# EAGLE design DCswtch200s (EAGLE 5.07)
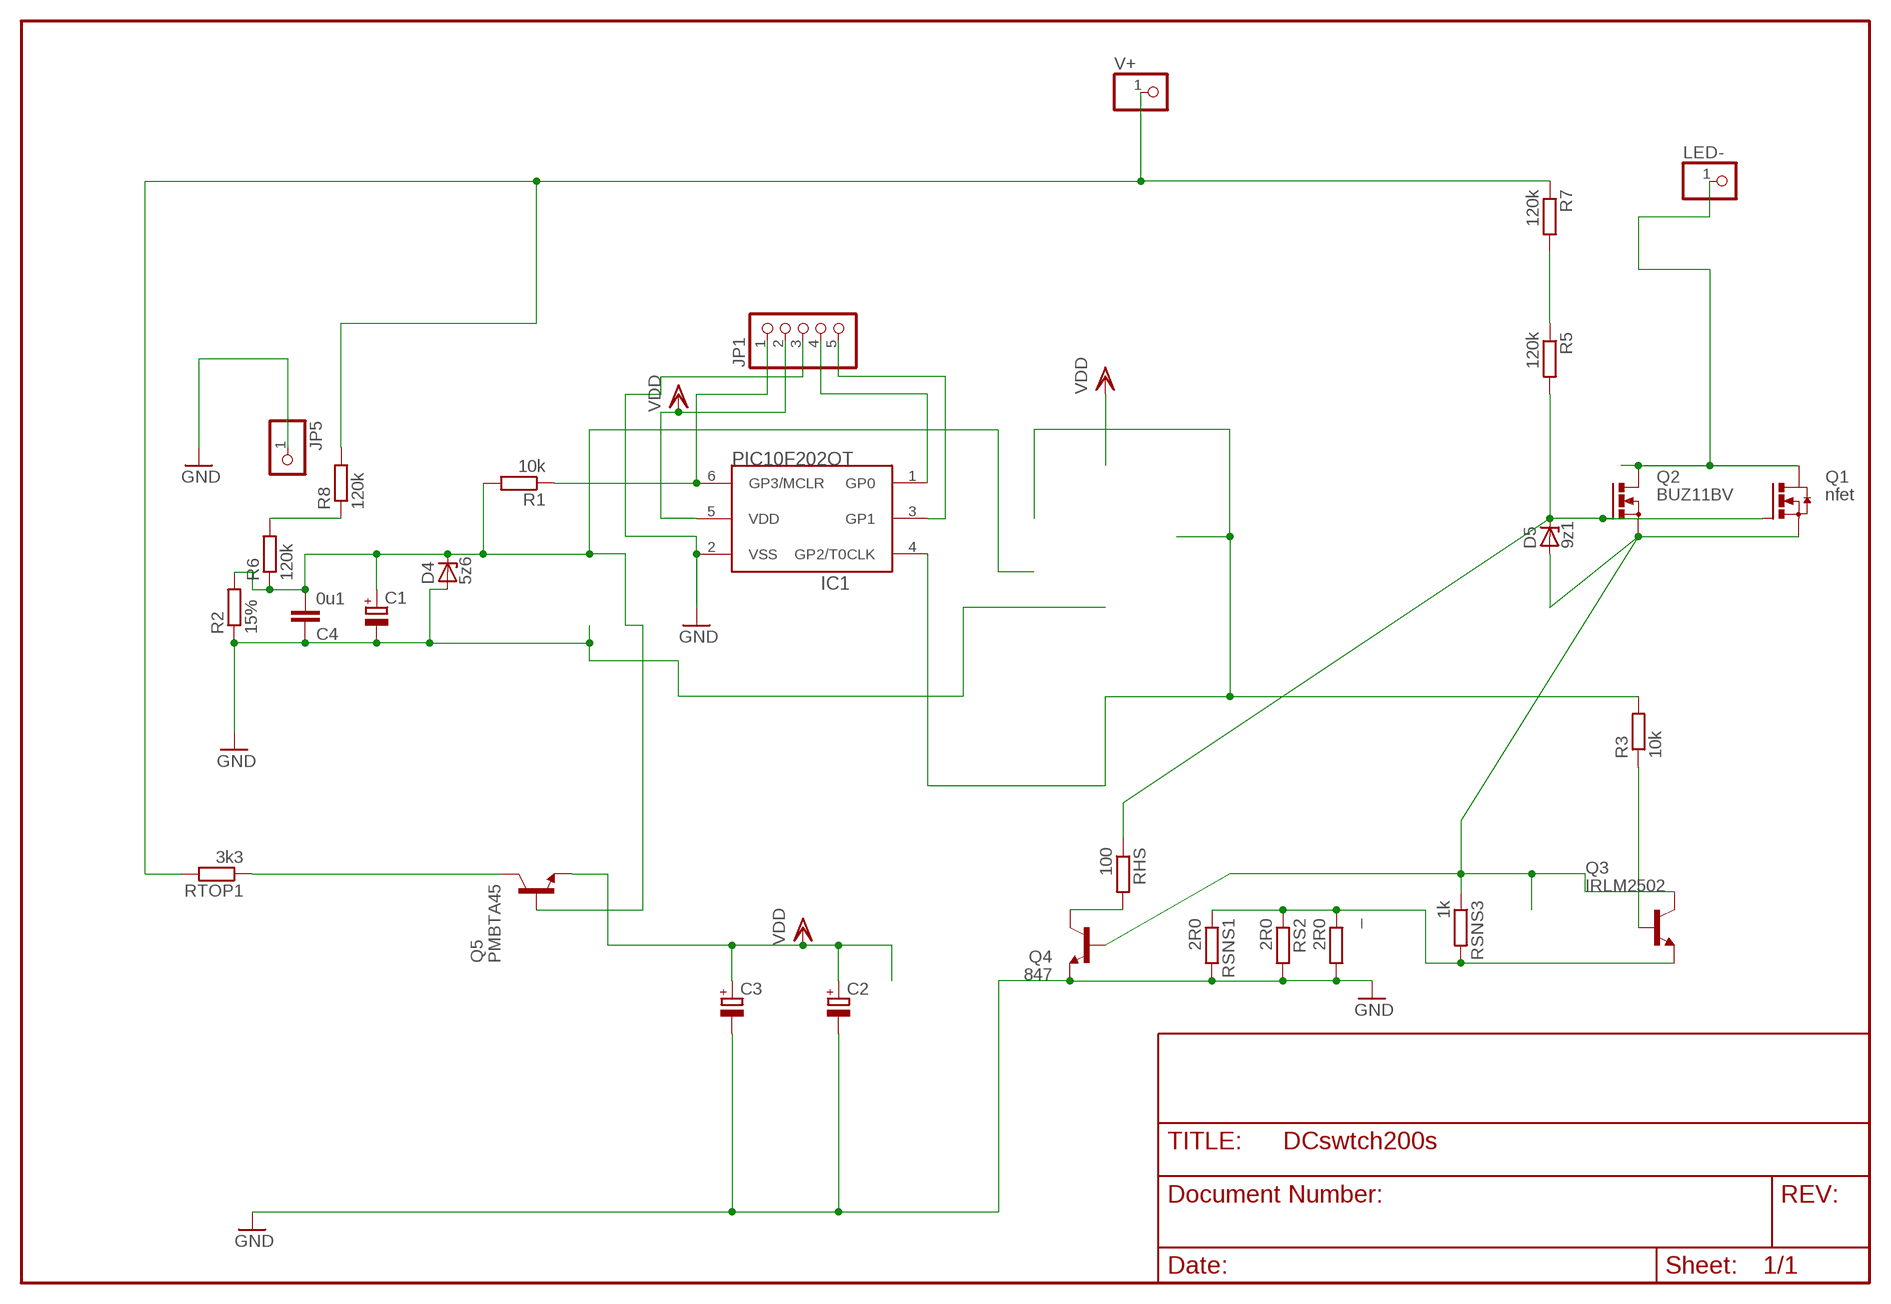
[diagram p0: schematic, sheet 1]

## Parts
_  2R0  R-EU_R2010  [R2010]
C1  CPOL-EUSMCA  [SMC_A]
C2  CPOL-EUE10-8.5  [E10-8.5]
C3  CPOL-EUE2,5-6E  [E2,5-6E]
C4  0u1  C-EUC1206  [C1206]
D4  5z6  ZENER-DIODESOD80C  [SOD80C]
D5  9z1  ZENER-DIODESOD80C  [SOD80C]
IC1  PIC10F202OT  [SOT23-6]
JP1  PINHD-1X5/90  [1X05/90]
JP5  PINHD-1X11MM6  [1X1MM8]
LED-  PINHD-1X11MM6  [1X1MM8]
Q1  nfet  N-HEXFET_DPAK-  [TO252]
Q2  BUZ11BV  [TO220BV]
Q3  IRLM2502  BC847ALT1SMD  [SOT23]
Q4  847  BC847ASMD  [SOT23]
Q5  PMBTA45  BC847ALT1SMD  [SOT23]
R1  10k  R-EU_R0805  [R0805]
R2  15%  R-EU_R0805  [R0805]
R3  10k  R-EU_R0805  [R0805]
R5  120k  R-EU_R1206  [R1206]
R6  120k  R-EU_R1206  [R1206]
R7  120k  R-EU_R1206  [R1206]
R8  120k  R-EU_R1206  [R1206]
RHS  100  R-EU_0204/5  [0204/5]
RS2  2R0  R-EU_R1206  [R1206]
RSNS1  2R0  R-EU_R2512  [R2512]
RSNS3  1k  R-EU_R1206  [R1206]
RTOP1  3k3  R-EU_R1206  [R1206]
V+  PINHD-1X11MM6  [1X1MM8]

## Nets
BSW1: _.1 Q3.2(E) RS2.1 RSNS1.1 RSNS3.2
C: Q5.3(C) RTOP1.1
CB: C1.+ C4.2 D4.C Q5.1(B) R1.2 R2.2 R6.1
G: D5.C Q1.1(G) Q2.G R5.2 RHS.1
GND: _.2 C1.- C2.- C3.- C4.1 D4.A IC1.2(VSS) JP1.3 JP5.1 Q4.2(E) R2.1 RS2.2 RSNS1.2
GP2: IC1.4(GP2/T0CLK) R3.2
LED-: LED-.1 Q1.3(D) Q2.D
N$3: IC1.6(GP3/MCLR) JP1.1 R1.1
N$4: R5.1 R7.2
N$5: Q3.1(B) R3.1
N$7: Q4.3(C) RHS.2
N$9: R6.2 R8.1
N$10: IC1.1(GP0) JP1.4
N$12: IC1.3(GP1) JP1.5
S: D5.A Q1.2(S) Q2.S Q3.3(C) Q4.1(B) RSNS3.1
VDD: C2.+ C3.+ IC1.5(VDD) JP1.2 Q5.2(E)
VPLUS: R7.1 R8.2 RTOP1.2 V+.1

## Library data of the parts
_ R3 R5 R7 RHS RS2 RSNS1 RSNS3 RTOP1 = rcl:R-EU_: RESISTOR, European symbol
C1-C3 = rcl:CPOL-EU: POLARIZED CAPACITOR, European symbol
C4 = rcl:C-EU: CAPACITOR, European symbol
D4 D5 = diode:ZENER-DIODE: Z-Diode
IC1 = microchip-5:PIC10F20*: uPC nW 0,25/0,5k Program Flash memory
JP1 = pinhead:PINHD-1X5: PIN HEADER
JP5 LED- V+ = pinhead:PINHD-1X1: PIN HEADER
Q1 = transistor-power:N-HEXFET_?-*: HEXFET® Power MOSFET
Q2 = transistor-power:BUZ11: N-CHANNEL MOS FET
Q3-Q5 = transistor-npn:BC847*: NPN Transistor
R1 R2 R6 R8 = rcl-2:R-EU_: RESISTOR, European symbol

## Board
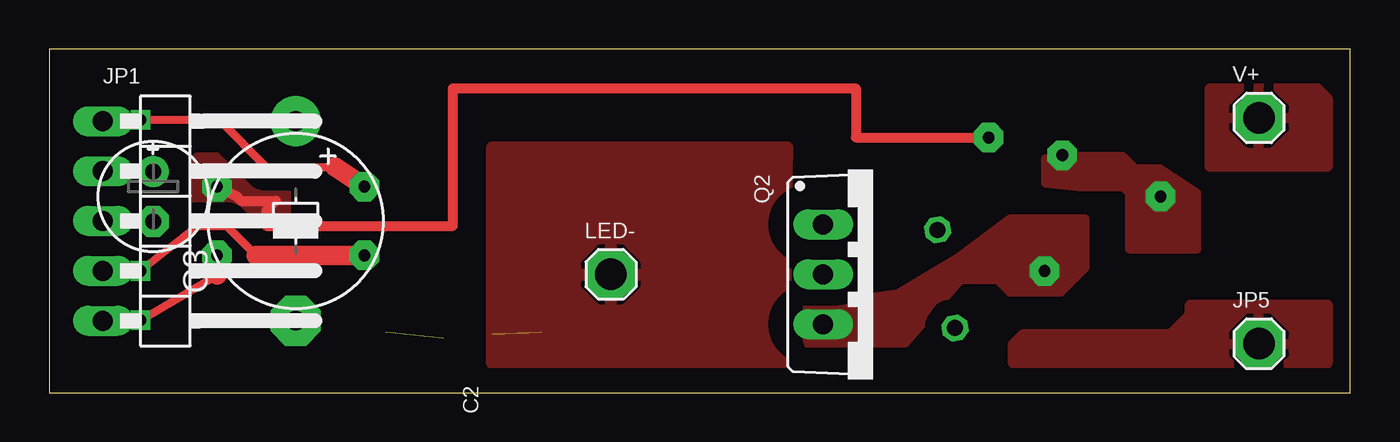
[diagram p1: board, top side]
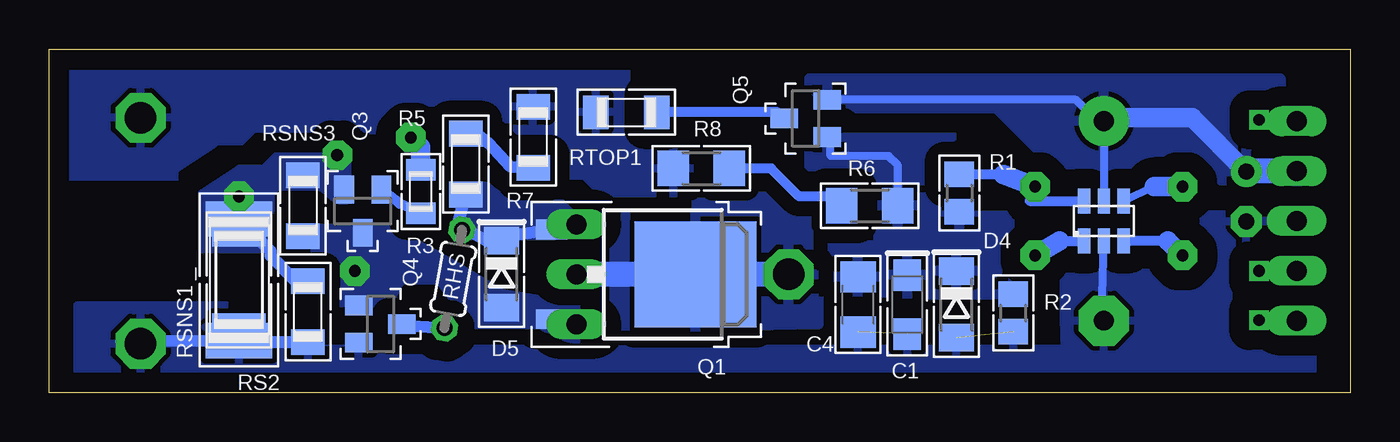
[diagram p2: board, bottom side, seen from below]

Size 66.2 x 17.5 mm. Coordinates in mm from the lower left corner, seen from the top.
Outline: 0,0 66.2,0 66.2,17.5 0,17.5 0,0
Copper layers (1*16): Top 0.035mm / dielectric 1.5mm / Bottom 0.035mm
Design rules "default *": minimum track width 10mil, minimum drill 24mil, track to track 8mil, track to pad 8mil, pad to pad 8mil, via to via 8mil, smd to smd 8mil, copper to edge 20mil, drill to drill 8mil, minimum pad ring 10mil, minimum via ring 8mil, stop-mask expansion 4mil, vias tented up to drill 0mil, thermal gap 10mil

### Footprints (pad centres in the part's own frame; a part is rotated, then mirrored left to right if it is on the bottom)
R2010 = smd 1.4 x 2.7: 1 -2.4,0; 2 2.4,0
SMC_A = smd 1.6 x 1.4: + -1.5,0; - 1.5,0
E10-8.5 = drill 1 pad 2.54 round: + -5.08,0 | drill 1 pad 2.54 octagon: - 5.08,0
E2,5-6E = drill 0.813 pad 1.575 round: + -1.27,0 | drill 0.813 pad 1.575 octagon: - 1.27,0
C1206 = smd 1.6 x 1.8: 1 -1.4,0; 2 1.4,0
SOD80C = smd 1.4 x 1.8: A 1.7,0; C -1.7,0
SOT23-6 = smd 0.635 x 1.27: 1 -1.016,-1.016; 2 0,-1.016; 3 1.016,-1.016; 4 1.016,1.016; 5 0,1.016; 6 -1.016,1.016
1X05/90 = drill 1.016 long: 1 -5.08,-3.81; 2 -2.54,-3.81; 3 0,-3.81; 4 2.54,-3.81; 5 5.08,-3.81
1X1MM8 = drill 1.6 pad 2.54 octagon: 1 0,0
TO252 = smd 1 x 1.6: 1 -2.28,-3.53; 2 2.28,-3.53 | smd 5.4 x 6.2: 3 0,3.77
TO220BV = drill 1.016 long: D 0,-2.54; G -2.54,-2.54; S 2.54,-2.54
SOT23 = smd 1 x 1.4: 1 -0.95,-1.1; 2 0.95,-1.1; 3 0,1.1
R0805 = smd 1.3 x 1.5: 1 -0.95,0; 2 0.95,0
R0805' = smd 1.1 x 1.5: 1 -1.1,0; 2 1.1,0
R1206 = smd 1.3 x 1.7: 1 -1.55,0; 2 1.55,0
R1206' = smd 1.6 x 1.803: 1 -1.422,0; 2 1.422,0
0204/5 = drill 0.813 octagon: 1 -2.54,0; 2 2.54,0
R2512 = smd 1.8 x 3.4: 1 -3.1,0; 2 3.1,0

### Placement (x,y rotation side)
_  56.54,5.75 270 bottom
C1  22.54,4.5 270 bottom
C2  12.54,8.75 270 top
C3  5.29,10 270 top
C4  25.04,4.5 90 bottom
D4  20.04,4.5 270 bottom
D5  43.18,6.03 270 bottom
IC1  12.54,8.75 0 bottom
JP1  6.54,8.75 270 top
JP5  61.54,2.5 0 top
LED-  28.57,6.03 0 top
Q1  37.08,6.03 270 bottom
Q2  41.91,6.03 270 top
Q3  50.24,9.25 180 bottom
Q4  49.34,3.5 270 bottom
Q5  27.71,13.97 90 bottom
R1  19.9,10.17 270 bottom
R2  17.14,4.06 90 bottom
R3  10k  [R0805']  47.29,10.25 90 bottom
R5  45,11.65 270 bottom
R6  120k  [R1206']  24.45,9.53 180 bottom
R7  41.57,13.02 270 bottom
R8  120k  [R1206']  33.02,11.43 180 bottom
RHS  45.64,5.8 260 bottom
RS2  53.02,4.13 270 bottom
RSNS1  56.54,5.75 270 bottom
RSNS3  53.29,9.53 90 bottom
RTOP1  36.83,14.29 180 bottom
V+  61.54,14 0 top

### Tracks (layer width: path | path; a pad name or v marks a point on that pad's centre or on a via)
BSW1  (via drill 0.6 pad 1.5)
  Bottom 0.61: RS2.1 53.62,5.68 54.93,6.99 54.93,7.23 RSNS1.1
  other vias: 56.54,10 51.54,12.1
  pour Bottom (isolate 0.813, rank 2, no thermals): 58.42,7.3 58.42,10.16 56.52,11.43 55.24,11.43 54.61,12.06 51.04,12.06 51.04,9.66 51.62,9.84 52.39,10.48 54.61,10.48 54.93,10.16 54.93,7.3
  pour Top (isolate 0.813, rank 2, no thermals): 58.42,7.3 58.42,10.16 56.52,11.43 55.24,11.43 54.61,12.06 51.44,12.06 50.66,11.93 50.66,10.66 52.39,10.48 54.61,10.48 54.93,10.16 54.93,7.3
C
  Bottom 0.5: RTOP1.1 29.13,14.29 Q5.3
CB
  Bottom 0.406: R6.1 23.02,11.6 23.49,12.06 26.44,12.06 26.44,12.85 Q5.1
  pour Bottom (isolate 1, rank 3): 19.54,13.5 27.54,13.5 27.54,11.5 24.04,11.5 24.04,7.5 26.54,7.5 26.54,5 17.04,5 17.04,9 21.04,9 21.04,12.5
G
  Bottom 0.61: 45.4,8.57 R5.2 | 45.4,8.57 RHS.1 | Q2.G 39.91,8.57 Q1.1 43.43,7.87 D5.C 43.93,7.73 45.4,8.57
  pour Bottom (isolate 1, rank 2, no thermals): 39.54,8.5 40.54,8 45.04,8 46.04,10.5 41.04,10.5 39.54,9
GND  (2 unrouted)
  Bottom 0.406: IC1.2 12.65,4.03 C2.- 13.35,3.11
  Bottom 0.61: RSNS1.2 _.2 | RS2.2 56.52,2.58 RSNS1.2 | RSNS1.2 62.55,2.62 JP5.1
  pour Bottom (isolate 1.016): 57.15,4.45 64.77,4.45 64.77,1 1.91,1 1.86,9.12 5.81,9.12 14.64,8.82 14.61,3.81 14.54,2.25 57.79,2.25
  pour Top (rank 2): 58.04,4.5 65.04,4.5 65.04,1.5 49.04,1.5 49.04,2.5 49.54,3 57.04,3 58.04,4
GP2  (via drill 0.6 pad 1.5)
  Top 0.5: v47.79,13 41.04,13 41.04,15.5 20.54,15.5 20.54,8.5 11.04,8.5 11.04,9.28 IC1.4 9.77,9.77 9.54,10 v8.54,10.5
  Bottom 0.406: 9.96,10.5 IC1.4
  Bottom 1: v8.54,10.5 9.96,10.5 | R3.2 47.29,12.5 v47.79,13
  pour Top (isolate 1, rank 2, no thermals): 7.54,12 9.04,12 12.04,10.5 12.04,8 7.54,8
LED-
  Bottom 1.27: Q2.D Q1.3 LED-.1
  pour Top (isolate 1.27): 22.54,12.5 37.54,12.5 37.46,8.26 37.46,1.27 22.54,1.5
  pour Bottom (isolate 0.75, rank 4): 27.04,12.5 37.54,12.5 37.46,8.26 37.46,3.27 27.04,3.5
N$3  (via drill 0.6, 0.6 pad 1.5)
  Top 0.406: v4.64,13.9 8.64,13.9 11.04,11.5 14.54,11.5
  Top 1: 14.54,11.5 v16.04,10.5
  Bottom 0.406: JP1.1 4.01,13.97 v4.64,13.9
  Bottom 0.5: IC1.6 16.31,9.77 v16.04,10.5 | 17.66,11.12 R1.1
  Bottom 1: v16.04,10.5 17.66,11.12
N$4
  Bottom 0.61: R7.2 42.71,11.49 43.81,12.7 44.62,13.34 R5.1
N$5
  Bottom 0.5: R3.1 48.37,9.64 Q3.1
N$7
  Bottom 0.61: Q4.3 47.76,3.41 RHS.2
N$9
  Bottom 0.5: R8.1 29.47,11.43 28.04,10 26.34,10 R6.2
N$10  (via drill 0.6, 0.6 pad 1.5)
  Top 0.406: 10.54,7 9.04,8.5 7.54,8.5 v4.64,6.2
  Top 1: 10.54,7 v16.04,7
  Bottom 0.406: v4.64,6.2 3.25,6.2 JP1.4
  Bottom 0.5: 14.81,7.73 IC1.1
  Bottom 1: v16.04,7 14.81,7.73
N$12  (via drill 0.6, 0.6 pad 1.5)
  Top 0.406: v4.64,3.7 8.54,6
  Top 1: 8.54,6 v8.54,7
  Bottom 0.406: v4.64,3.7 2.73,3.7 JP1.5
  Bottom 0.5: 9.27,7.73 IC1.3
  Bottom 1: v8.54,7 9.27,7.73
S  (via drill 0.6 pad 1.5)
  Bottom 0.61: Q1.2 39.55,3.31 Q2.S
  other vias: 50.64,6.2
  pour Bottom (isolate 0.813, rank 3, no thermals): 39.37,4.45 43.18,5.08 46.35,6.99 48.89,8.39 52.7,8.39 52.7,6.35 51.44,4.58 48.89,4.58 48.26,5.71 46.35,5.71 44.45,3.17 39.37,2.54
  pour Top (isolate 0.813, rank 3, no thermals): 38.54,4.45 43.18,5.08 46.35,6.99 48.89,8.89 52.7,8.89 52.7,6.35 51.44,5.08 48.89,5.08 48.26,5.71 46.35,5.71 43.54,2.5 38.54,2.5
VDD
  Bottom 0.406: 12.46,14 C2.+ 12.54,13.5 | 12.54,13.5 IC1.5 | Q5.2 13.96,14.92 12.54,13.5
  Bottom 1: C3.+ 5.31,11.27 8.04,14 12.37,14 C2.+
  Bottom 1.27: JP1.2 5.27,11.29 C3.+
  pour Bottom (isolate 1, rank 2): 3.54,16 27.54,16 27.54,14.5 18.04,14.5 13.04,9.5 12.04,9.5 12.04,10.5 8.54,12 6.04,10.5 2.54,10.5 2.04,11
VPLUS
  pour Bottom (isolate 1.016, rank 3): 30.48,13.34 36.83,13.34 36.83,16.5 65.41,16.5 65.54,11 39.54,11 39.46,10.16 29.21,10.16 29.21,11.43 30.48,11.43
  pour Top (rank 2): 59.04,15.5 64.54,15.5 65.04,15 65.04,11.5 59.04,11.5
